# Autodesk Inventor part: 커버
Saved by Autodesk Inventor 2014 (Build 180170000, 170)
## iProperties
Created: 2025-09
Part Number: 커버
Material: 일반
Document SubType Name: Modeling
Designer: dg
Density: 1 g/cm^3
Appearance: 기본값
Author: dg
Author: jhkim
Creation Date: 2025-09-02
Sending System: Autodesk Inventor 2026
Preprocessor: ST-DEVELOPER v20.1
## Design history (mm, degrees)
node "커버1"
node "솔리드1"
node "기준1"
